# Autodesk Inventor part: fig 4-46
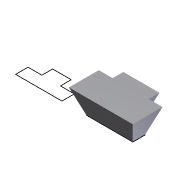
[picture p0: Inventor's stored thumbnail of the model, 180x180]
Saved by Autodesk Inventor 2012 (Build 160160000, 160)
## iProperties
Created: 2004-05
Part Number: fig 4-46
Document SubType Name: Modeling
Designer: CADCIM Technologies
Manufacturer: Standard
Standards Organization: Custom
Density: 1 g/cm^3
Material: Default
Author: CADCIM Technologies
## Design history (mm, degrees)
sketch "Sketch1"
  geometry: L1 (31.783, 34.561)-(31.783, 22.933); L2 (31.783, 22.933)-(16.796, 22.933); L3 (16.796, 22.933)-(16.796, 9.496); L4 (16.796, 9.496)-(66.925, 9.496); L5 (66.925, 9.496)-(66.925, 22.933); L6 (66.925, 22.933)-(51.938, 22.933); L7 (51.938, 22.933)-(51.938, 34.561); L8 (51.938, 34.561)-(31.783, 34.561); L9 (-45.013, 34.561)-(-45.013, 22.933); L10 (-45.013, 22.933)-(-60, 22.933); L11 (-60, 22.933)-(-60, 9.496); L12 (-60, 9.496)-(-9.871, 9.496); L13 (-9.871, 9.496)-(-9.871, 22.933); L14 (-9.871, 22.933)-(-24.858, 22.933); L15 (-24.858, 22.933)-(-24.858, 34.561); L16 (-24.858, 34.561)-(-45.013, 34.561)
  constraints: 32 end point, 10 parallel, 4 equal length, 2 collinear, 2 perpendicular, 2 vertical
extrude "Extrusion2" new body sketch "Sketch1" distance "d2" = 26; taper "d3" = 20 deg
body "Solid2"
